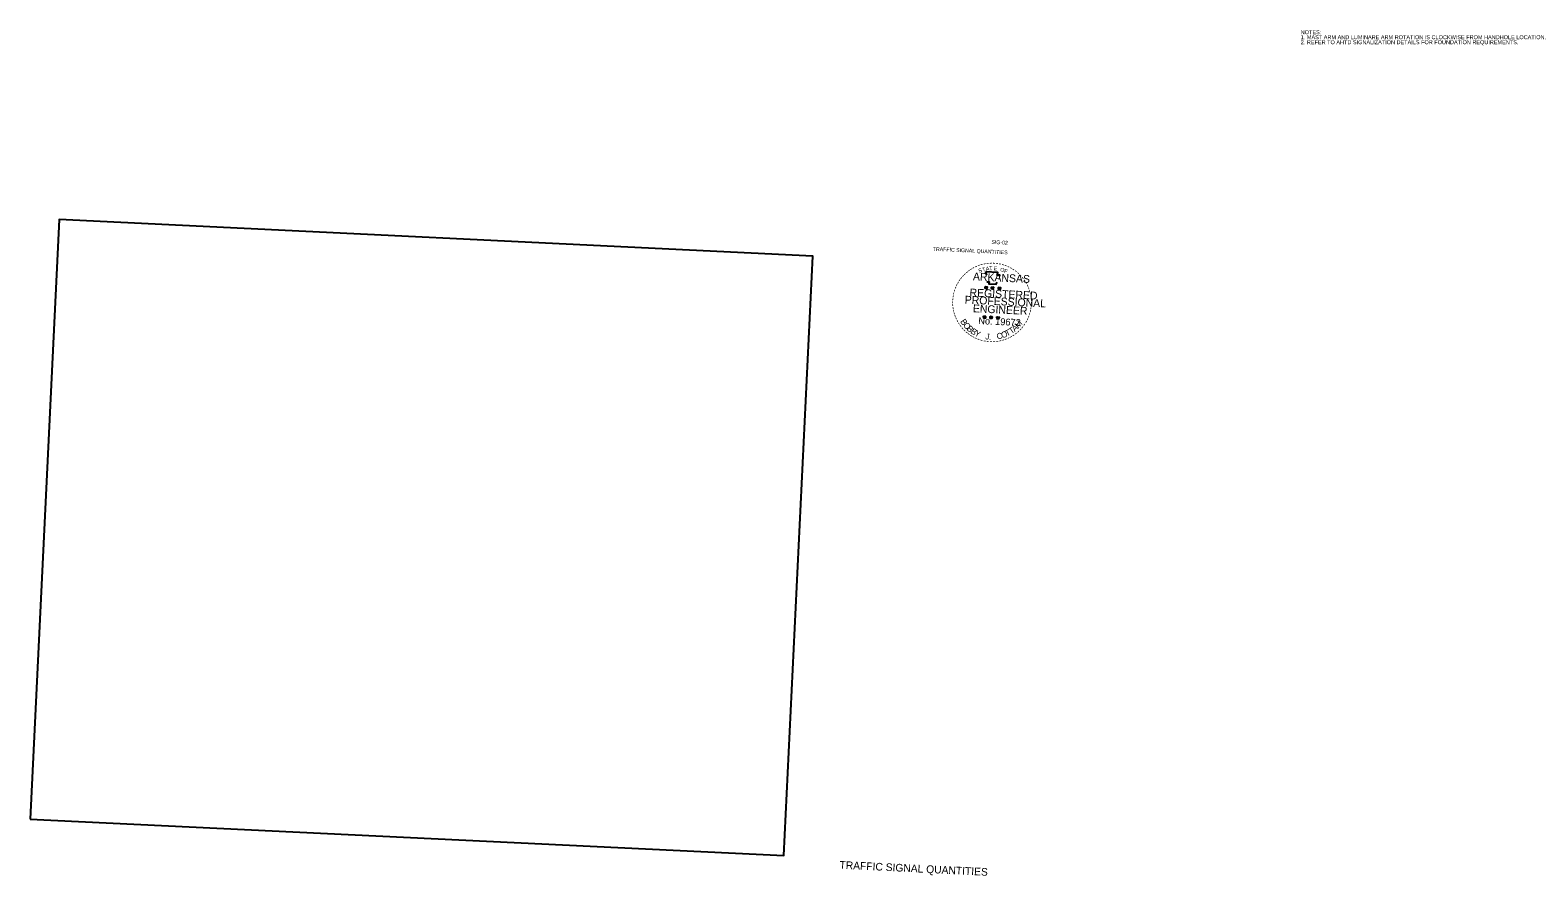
# Model space of a CAD drawing. Extents: x 661030 to 662601, y 642184 to 643065.
# Drawn here: x 661659 to 662601, y 642536 to 643065 of the extents above; entities that cross this region are included whole.
import ezdxf

# ---------------------------------------------------------------- set-up
doc = ezdxf.new("R2010")
doc.units = 0
for name, color, linetype in [('R_Border', 7, 'Continuous'), ('R_Horz Alg Annot', 7, 'Continuous'), ('T_Detection Zones', 7, 'Continuous'), ('TEXT', 7, 'Continuous')]:
    doc.layers.add(name, color=color, linetype=linetype)

msp = doc.modelspace()

# ---------------------------------------------------------------- linework, layer by layer
at = {"layer": 'R_Border'}
for p, q in [((662255.39, 642904.23), (662256.23, 642903.92)), ((662255.39, 642904.23), (662256.01, 642904.09)), ((662255.39, 642904.23), (662255.96, 642903.9)), ((662255.67, 642903.22), (662256.23, 642903.92)), ((662255.67, 642903.22), (662256.01, 642903.8)), ((662255.67, 642903.22), (662256.22, 642903.72)), ((662256.27, 642904.81), (662256.14, 642904.2)), ((662256.72, 642903.17), (662256.22, 642903.72)), ((662256.23, 642903.92), (662256.27, 642904.81)), ((662257.09, 642904.15), (662256.23, 642903.92)), ((662256.72, 642903.17), (662256.23, 642903.92)), ((662256.27, 642904.81), (662256.36, 642904.19)), ((662257.09, 642904.15), (662256.39, 642904.06)), ((662256.72, 642903.17), (662256.42, 642903.89)), ((662257.09, 642904.15), (662256.58, 642903.92)), ((662259.47, 642904.03), (662260.3, 642903.72)), ((662259.47, 642904.03), (662260.08, 642903.89)), ((662259.47, 642904.03), (662260.03, 642903.71)), ((662259.74, 642903.02), (662260.3, 642903.72)), ((662259.74, 642903.02), (662260.08, 642903.6)), ((662259.74, 642903.02), (662260.29, 642903.53)), ((662260.35, 642904.61), (662260.22, 642904)), ((662260.79, 642902.97), (662260.29, 642903.52)), ((662260.3, 642903.72), (662260.35, 642904.61)), ((662261.16, 642903.95), (662260.3, 642903.72)), ((662260.79, 642902.97), (662260.3, 642903.72)), ((662260.35, 642904.61), (662260.44, 642903.99)), ((662261.16, 642903.95), (662260.46, 642903.86)), ((662260.79, 642902.97), (662260.49, 642903.7)), ((662261.16, 642903.95), (662260.65, 642903.72)), ((662263.77, 642903.79), (662264.6, 642903.48)), ((662263.77, 642903.79), (662264.38, 642903.65)), ((662263.77, 642903.79), (662264.33, 642903.47)), ((662264.04, 642902.78), (662264.6, 642903.48)), ((662264.04, 642902.78), (662264.38, 642903.36)), ((662264.04, 642902.78), (662264.59, 642903.29)), ((662264.65, 642904.37), (662264.52, 642903.76)), ((662265.09, 642902.73), (662264.59, 642903.28)), ((662264.6, 642903.48), (662264.65, 642904.37)), ((662265.46, 642903.71), (662264.6, 642903.48)), ((662265.09, 642902.73), (662264.6, 642903.48)), ((662264.65, 642904.37), (662264.74, 642903.76)), ((662265.46, 642903.71), (662264.76, 642903.63)), ((662265.09, 642902.73), (662264.79, 642903.46)), ((662265.46, 642903.71), (662264.95, 642903.49)), ((662254.49, 642885.76), (662255.32, 642885.45)), ((662254.49, 642885.76), (662255.1, 642885.62)), ((662254.49, 642885.76), (662255.05, 642885.44)), ((662254.76, 642884.75), (662255.32, 642885.45)), ((662254.76, 642884.75), (662255.1, 642885.33)), ((662254.76, 642884.75), (662255.31, 642885.25)), ((662255.37, 642886.34), (662255.24, 642885.73)), ((662255.81, 642884.7), (662255.31, 642885.25)), ((662255.32, 642885.45), (662255.37, 642886.34)), ((662256.18, 642885.68), (662255.32, 642885.45)), ((662255.81, 642884.7), (662255.32, 642885.45)), ((662255.37, 642886.34), (662255.46, 642885.72)), ((662256.18, 642885.68), (662255.48, 642885.59)), ((662255.81, 642884.7), (662255.51, 642885.43)), ((662256.18, 642885.68), (662255.67, 642885.45)), ((662258.56, 642885.56), (662259.39, 642885.25)), ((662258.56, 642885.56), (662259.17, 642885.42)), ((662258.56, 642885.56), (662259.12, 642885.24)), ((662258.83, 642884.55), (662259.39, 642885.25)), ((662258.83, 642884.55), (662259.17, 642885.13)), ((662258.83, 642884.55), (662259.38, 642885.06)), ((662259.44, 642886.14), (662259.31, 642885.53)), ((662259.88, 642884.5), (662259.38, 642885.05)), ((662259.39, 642885.25), (662259.44, 642886.14)), ((662260.25, 642885.48), (662259.39, 642885.25)), ((662259.88, 642884.5), (662259.39, 642885.25)), ((662259.44, 642886.14), (662259.53, 642885.53)), ((662260.25, 642885.48), (662259.55, 642885.4)), ((662259.88, 642884.5), (662259.58, 642885.23)), ((662260.25, 642885.48), (662259.74, 642885.26)), ((662262.86, 642885.33), (662263.7, 642885.02)), ((662262.86, 642885.33), (662263.48, 642885.19)), ((662262.86, 642885.33), (662263.43, 642885)), ((662263.14, 642884.32), (662263.7, 642885.02)), ((662263.14, 642884.32), (662263.48, 642884.9)), ((662263.14, 642884.32), (662263.69, 642884.82)), ((662263.75, 642885.91), (662263.62, 642885.3)), ((662264.19, 642884.27), (662263.69, 642884.82)), ((662263.7, 642885.02), (662263.75, 642885.91)), ((662264.56, 642885.25), (662263.7, 642885.02)), ((662264.19, 642884.27), (662263.7, 642885.02)), ((662263.75, 642885.91), (662263.84, 642885.29)), ((662264.56, 642885.25), (662263.86, 642885.16)), ((662264.19, 642884.27), (662263.89, 642884.99)), ((662264.56, 642885.25), (662264.05, 642885.02))]:
    msp.add_line(p, q, dxfattribs=at)
for points in [[(662255.95, 642913.68), (662256.51, 642911.63)], [(662264.41, 642911.02), (662264.79, 642911.69), (662263.11, 642911.72), (662263.55, 642913.31), (662255.95, 642913.68)], [(662256.87, 642907.72), (662256.86, 642907.5), (662258.23, 642907.39), (662258.04, 642906.24), (662262.6, 642906.02), (662263.15, 642907.3)], [(662256.27, 642904.81), (662256.72, 642903.17), (662255.39, 642904.23), (662257.09, 642904.15), (662255.67, 642903.22), (662256.27, 642904.81)], [(662260.35, 642904.61), (662260.79, 642902.97), (662259.47, 642904.03), (662261.16, 642903.95), (662259.74, 642903.02), (662260.35, 642904.61)], [(662264.65, 642904.37), (662265.09, 642902.73), (662263.77, 642903.79), (662265.46, 642903.71), (662264.04, 642902.78), (662264.65, 642904.37)], [(662255.37, 642886.34), (662255.81, 642884.7), (662254.49, 642885.76), (662256.18, 642885.68), (662254.76, 642884.75), (662255.37, 642886.34)], [(662259.44, 642886.14), (662259.88, 642884.5), (662258.56, 642885.56), (662260.25, 642885.48), (662258.83, 642884.55), (662259.44, 642886.14)], [(662263.75, 642885.91), (662264.19, 642884.27), (662262.86, 642885.33), (662264.56, 642885.25), (662263.14, 642884.32), (662263.75, 642885.91)]]:
    msp.add_lwpolyline(points, dxfattribs=at)
for centre, radius in [((662256.23, 642903.92), 0.421), ((662256.23, 642903.92), 0.353), ((662256.23, 642903.92), 0.283), ((662256.23, 642903.92), 0.242), ((662256.23, 642903.92), 0.182), ((662256.23, 642903.92), 0.121), ((662256.23, 642903.92), 0.0724), ((662260.3, 642903.72), 0.421), ((662260.3, 642903.72), 0.353), ((662260.3, 642903.72), 0.283), ((662260.3, 642903.72), 0.242), ((662260.3, 642903.72), 0.182), ((662260.3, 642903.72), 0.121), ((662260.3, 642903.72), 0.0724), ((662264.6, 642903.48), 0.421), ((662264.6, 642903.48), 0.353), ((662264.6, 642903.48), 0.283), ((662264.6, 642903.48), 0.242), ((662264.6, 642903.48), 0.182), ((662264.6, 642903.48), 0.121), ((662264.6, 642903.48), 0.0724), ((662255.32, 642885.45), 0.421), ((662255.32, 642885.45), 0.353), ((662255.32, 642885.45), 0.283), ((662255.32, 642885.45), 0.242), ((662255.32, 642885.45), 0.182), ((662255.32, 642885.45), 0.121), ((662255.32, 642885.45), 0.0724), ((662259.39, 642885.25), 0.421), ((662259.39, 642885.25), 0.353), ((662259.39, 642885.25), 0.283), ((662259.39, 642885.25), 0.242), ((662259.39, 642885.25), 0.182), ((662259.39, 642885.25), 0.121), ((662259.39, 642885.25), 0.0724), ((662263.7, 642885.02), 0.421), ((662263.7, 642885.02), 0.353), ((662263.7, 642885.02), 0.283), ((662263.7, 642885.02), 0.242), ((662263.7, 642885.02), 0.182), ((662263.7, 642885.02), 0.121), ((662263.7, 642885.02), 0.0724)]:
    msp.add_circle(centre, radius, dxfattribs=at)
at = {"layer": 'T_Detection Zones'}
msp.add_lwpolyline([(661659.18, 642571.77), (662129.89, 642548.91), (662148.08, 642923.53), (661677.37, 642946.39)], close=True, dxfattribs=at)

# ---------------------------------------------------------------- texts
at = {"layer": 'R_Border'}
for s, height, rotation, p in [('TRAFFIC SIGNAL QUANTITIES', 2.3448, 357.21992, (662222.98, 642926.94)), ('SIG-02', 2.345, 357.21992, (662259.56, 642931.2)), ('-', 3.91, 33.45007, (662246.92, 642913.57)), ('-', 3.91, 31.2819, (662248.37, 642914.47)), ('-', 3.91, 26.01015, (662249.87, 642915.3)), ('-', 3.91, 21.52555, (662251.46, 642916)), ('S', 2.44, 18.81235, (662251.9, 642913.09)), ('-', 3.91, 16.39442, (662253.03, 642916.58)), ('T', 2.44, 13.62193, (662254.17, 642913.79)), ('-', 3.91, 10.84848, (662254.89, 642917.08)), ('A', 2.44, 8.43151, (662256.22, 642914.31)), ('-', 3.91, 7.43768, (662256.56, 642917.39)), ('T', 2.44, 3.24109, (662258.31, 642914.61)), ('-', 3.91, 3.11516, (662258.35, 642917.57)), ('-', 3.91, 357.40456, (662260.25, 642917.66)), ('E', 2.44, 358.05067, (662261.01, 642914.75)), ('-', 3.91, 354.96138, (662262.01, 642917.54)), ('-', 3.91, 349.38006, (662263.82, 642917.32)), ('O', 2.44, 347.66983, (662264.9, 642914.04)), ('-', 3.91, 344.42323, (662265.56, 642916.95)), ('F', 2.44, 337.289, (662267.2, 642913.38)), ('-', 3.91, 339.55453, (662267.09, 642916.5)), ('-', 3.91, 335.07343, (662268.85, 642915.87)), ('-', 3.91, 331.33943, (662270.36, 642915.13)), ('-', 3.91, 326.85923, (662271.74, 642914.38)), ('-', 3.91, 64.9926, (662238.95, 642903.99)), ('-', 3.91, 60.08968, (662239.65, 642905.45)), ('-', 3.91, 55.28896, (662240.49, 642906.91)), ('-', 3.91, 51.45081, (662241.34, 642908.16)), ('-', 3.91, 47.83251, (662242.42, 642909.49)), ('-', 3.91, 45.64138, (662243.46, 642910.63)), ('-', 3.91, 40.18058, (662244.61, 642911.74)), ('-', 3.91, 36.16899, (662245.71, 642912.71)), ('ARKANSAS', 4.883, 357.21833, (662248.01, 642908.48)), ('-', 3.91, 323.08099, (662273.26, 642913.42)), ('-', 3.91, 317.74804, (662274.7, 642912.31)), ('-', 3.91, 312.79692, (662276.1, 642911.05)), ('-', 3.91, 307.09806, (662277.42, 642909.64)), ('-', 3.91, 303.87051, (662278.63, 642908.11)), ('-', 3.42, 300.89363, (662279.75, 642906.66)), ('-', 3.91, 86.28057, (662236.96, 642895.66)), ('-', 3.91, 82.40467, (662237.1, 642897.36)), ('-', 3.91, 78.4196, (662237.37, 642899.04)), ('-', 3.91, 72.67929, (662237.77, 642900.76)), ('-', 3.91, 69.61281, (662238.34, 642902.48)), ('PROFESSIONAL', 4.8833, 357.21833, (662242.84, 642893.93)), ('REGISTERED', 4.883, 357.21833, (662245.86, 642898.44)), ('-', 3.91, 296.88669, (662280.46, 642905.15)), ('-', 3.91, 291.88113, (662281.18, 642903.62)), ('-', 3.91, 287.79116, (662281.73, 642902.18)), ('-', 3.91, 282.3416, (662282.24, 642900.74)), ('-', 3.91, 277.76767, (662282.64, 642898.9)), ('-', 3.91, 273.81449, (662282.94, 642897.01)), ('-', 3.91, 96.16626, (662237.05, 642892.25)), ('-', 3.91, 91.41422, (662236.96, 642893.89)), ('-', 3.91, 98.93328, (662237.29, 642890.45)), ('-', 3.91, 102.67618, (662237.62, 642888.98)), ('-', 3.91, 106.30575, (662238.07, 642887.41)), ('ENGINEER', 4.883, 357.21833, (662247.92, 642888.49)), ('-', 3.91, 252.98094, (662282.28, 642888.85)), ('-', 3.91, 258.21362, (662282.63, 642890.49)), ('-', 3.91, 260.73553, (662282.88, 642892.07)), ('-', 3.91, 267.159, (662283.01, 642893.7)), ('-', 3.91, 271.54844, (662283, 642895.24)), ('-', 3.91, 111.28265, (662238.62, 642885.93)), ('-', 3.91, 112.94718, (662239.29, 642884.39)), ('-', 3.91, 117.66545, (662240.09, 642882.91)), ('-', 3.91, 123.11178, (662241.01, 642881.5)), ('-', 3.91, 127.93645, (662242.07, 642880.1)), ('B', 3.76, 304.07319, (662239.95, 642882.68)), ('-', 3.91, 131.44215, (662243.26, 642878.71)), ('O', 3.76, 312.18337, (662241.68, 642880.12)), ('B', 3.76, 317.96399, (662243.8, 642877.79)), ('B', 3.76, 326.07417, (662246.23, 642875.71)), ('No. 19672', 4.29, 357.21833, (662251.35, 642881.11)), ('T', 3.76, 27.35609, (662269.32, 642873.24)), ('T', 3.76, 34.23693, (662272.02, 642874.7)), ('A', 3.76, 40.13725, (662274.17, 642876.16)), ('M', 3.76, 48.24743, (662276.53, 642878.17)), ('-', 3.91, 228.47211, (662277.2, 642879.33)), ('-', 3.91, 231.06358, (662278.31, 642880.66)), ('-', 3.91, 236.28958, (662279.37, 642882.21)), ('-', 3.91, 241.83805, (662280.42, 642884)), ('-', 3.91, 245.107, (662281.13, 642885.5)), ('-', 3.91, 250.08642, (662281.76, 642887.11)), ('-', 3.91, 136.15216, (662244.49, 642877.51)), ('-', 3.91, 141.86467, (662245.8, 642876.46)), ('-', 3.91, 145.30812, (662247.12, 642875.49)), ('-', 3.91, 148.78873, (662248.49, 642874.62)), ('-', 3.91, 151.81853, (662249.74, 642873.96)), ('-', 3.91, 155.77955, (662251.23, 642873.27)), ('Y', 3.76, 334.18435, (662248.71, 642874.11)), ('-', 3.91, 160.0166, (662252.88, 642872.67)), ('-', 3.91, 164.77385, (662254.6, 642872.18)), ('-', 3.91, 170.3338, (662256.47, 642871.82)), ('J', 3.76, 350.5606, (662255.61, 642871.66)), ('-', 3.91, 173.7366, (662258.29, 642871.6)), ('.', 3.76, 350.5606, (662257.9, 642871.36)), ('-', 3.91, 178.62152, (662260.24, 642871.55)), ('-', 3.91, 183.035, (662262.09, 642871.65)), ('-', 3.91, 188.50409, (662263.9, 642871.89)), ('C', 3.76, 11.13573, (662263.27, 642871.47)), ('-', 3.91, 192.69263, (662265.7, 642872.29)), ('O', 3.76, 19.24591, (662266.38, 642872.16)), ('-', 3.91, 197.93676, (662267.38, 642872.8)), ('-', 3.91, 201.46995, (662268.92, 642873.39)), ('-', 3.91, 204.57517, (662270.48, 642874.09)), ('-', 3.91, 209.46742, (662271.89, 642874.87)), ('-', 3.91, 212.95467, (662273.23, 642875.75)), ('-', 3.91, 218.30342, (662274.63, 642876.84)), ('-', 3.91, 222.98367, (662275.96, 642878.02))]:
    msp.add_text(s, height=height, rotation=rotation, dxfattribs=at).set_placement(p)
at = {"layer": 'R_Horz Alg Annot'}
msp.add_text('TRAFFIC SIGNAL QUANTITIES', height=4.8, rotation=357.21992, dxfattribs=at).set_placement((662164.62, 642540.76))
at = {"layer": 'TEXT'}
for s, p in [('2. REFER TO AHTD SIGNALIZATION DETAILS FOR FOUNDATION REQUIREMENTS.', (662452.8, 643055.97)), ('1. MAST ARM AND LUMINARE ARM ROTATION IS CLOCKWISE FROM HANDHOLE LOCATION.', (662452.8, 643059.1)), ('NOTES:', (662452.8, 643062.23))]:
    msp.add_text(s, height=2.5, rotation=360, dxfattribs=at).set_placement(p)

doc.saveas('drawing.dxf')
